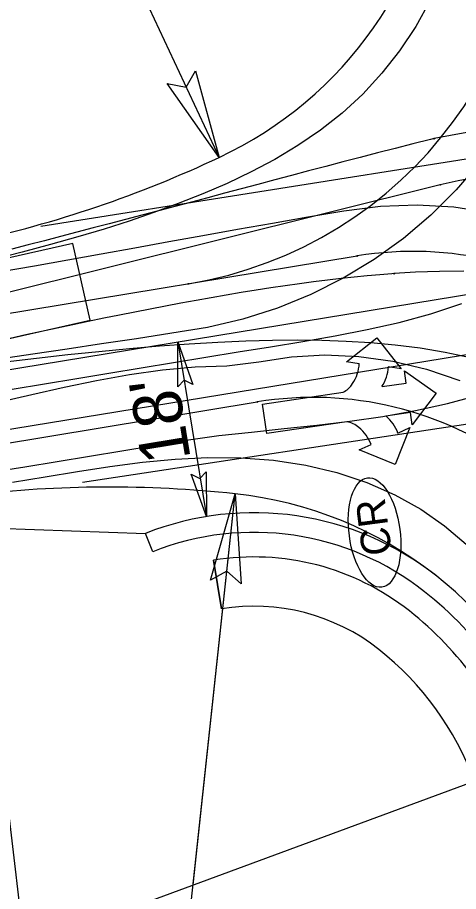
# Model space of a CAD drawing. Extents: x 2367848 to 2369479, y 800728 to 808616.
# Drawn here: x 2368311.6 to 2368356.4, y 807886 to 807974.9 of the extents above; entities that cross this region are included whole.
import ezdxf

# ---------------------------------------------------------------- set-up
doc = ezdxf.new("R2010")
doc.units = 0
for name, color, linetype in [('Default', 7, 'Continuous'), ('Prop AutoTurn Projected Path', 7, 'Continuous'), ('Prop AutoTurn Simulation', 7, 'Continuous'), ('Prop Conc 2ft 6in Curb and Gutter', 7, 'Continuous'), ('Prop Conc 4in Sidewalk', 7, 'Continuous'), ('Prop Dimension', 7, 'Continuous'), ('Prop Dimension Text', 7, 'Continuous'), ('Prop EOT', 7, 'Continuous'), ('Prop Horizontal Alignment', 7, 'Continuous'), ('Prop Lane Arrow CELL', 7, 'Continuous'), ('Prop Paved Shoulder', 7, 'Continuous'), ('Prop Shade Light', 7, 'Continuous'), ('Prop Terminator CELL', 7, 'Continuous'), ('Prop WCC CELL', 7, 'Continuous'), ('Prop WCR CELL', 7, 'Continuous'), ('Scratch_Level_0', 7, 'Continuous'), ('Scratch_Level_1', 7, 'Continuous')]:
    doc.layers.add(name, color=color, linetype=linetype)

# ---------------------------------------------------------------- blocks, each defined once
blk = doc.blocks.new('CR')
at = {"layer": 'Prop WCC CELL'}
blk.add_ellipse((0.022, -0.023), major_axis=(5.607, 0), ratio=0.462467, dxfattribs=at)
blk.add_text('CR', height=3, dxfattribs=at).set_placement((-2.335, -1.5))

msp = doc.modelspace()

# ---------------------------------------------------------------- linework, layer by layer
at = {"layer": 'Default'}
for p, q in [((2368447.259, 807974.784), (2368313.924, 807953.632)), ((2368318.181, 807927.648), (2368451.676, 807947.822))]:
    msp.add_line(p, q, dxfattribs=at)
at = {"layer": 'Prop AutoTurn Projected Path'}
for p, q in [((2368204.585, 807927.346), (2368346.13, 807950.643)), ((2368301.356, 807930.099), (2368335.962, 807935.795))]:
    msp.add_line(p, q, dxfattribs=at)
for centre, radius, start, end in [((2368322.121, 807989.257), 42, 279.34665, 7.41804), ((2368351.814, 807916.108), 35, 7.41804, 99.34665), ((2368341.646, 807901.26), 35, 7.41804, 99.34665)]:
    msp.add_arc(centre, radius, start, end, dxfattribs=at)
at = {"layer": 'Prop AutoTurn Simulation'}
for points in [[(2368353.558, 807976.632), (2368352.084, 807973.994), (2368350.439, 807971.521), (2368348.636, 807969.222), (2368346.685, 807967.102), (2368344.601, 807965.17), (2368342.398, 807963.43), (2368340.099, 807961.871), (2368337.733, 807960.465), (2368335.321, 807959.189), (2368332.876, 807958.024), (2368330.408, 807956.954), (2368327.922, 807955.967), (2368325.423, 807955.049), (2368322.915, 807954.193), (2368320.378, 807953.384), (2368317.71, 807952.585), (2368314.924, 807951.799), (2368312.042, 807951.032), (2368309.084, 807950.286)], [(2368358.574, 807960.118), (2368356.202, 807957.36), (2368353.612, 807954.79), (2368350.82, 807952.426), (2368347.845, 807950.284), (2368344.704, 807948.379), (2368341.417, 807946.725), (2368338.005, 807945.335), (2368334.489, 807944.216), (2368330.892, 807943.378), (2368327.26, 807942.782), (2368323.668, 807942.231), (2368320.117, 807941.697), (2368316.602, 807941.174), (2368313.119, 807940.657), (2368309.664, 807940.143)], [(2368359.637, 807955.047), (2368355.952, 807955.609), (2368352.223, 807955.823), (2368348.483, 807955.684), (2368344.769, 807955.199), (2368341.112, 807954.588), (2368337.507, 807953.962), (2368333.949, 807953.33), (2368330.431, 807952.697), (2368326.948, 807952.067), (2368323.496, 807951.443), (2368320.068, 807950.826), (2368316.662, 807950.216), (2368313.273, 807949.613), (2368309.9, 807949.017)], [(2368357.642, 807940.281), (2368355.074, 807940.837), (2368352.521, 807941.262), (2368349.989, 807941.579), (2368347.48, 807941.806), (2368344.993, 807941.956), (2368342.528, 807942.042), (2368340.081, 807942.072), (2368337.517, 807942.052), (2368334.798, 807941.98), (2368331.957, 807941.857), (2368329.02, 807941.684), (2368326.009, 807941.464), (2368322.939, 807941.203), (2368319.824, 807940.905), (2368316.674, 807940.573), (2368313.496, 807940.212), (2368310.296, 807939.826)], [(2368309.726, 807935.801), (2368313, 807936.559), (2368316.29, 807937.304), (2368319.606, 807937.992), (2368322.947, 807938.586), (2368326.296, 807939.054), (2368329.623, 807939.375), (2368332.865, 807939.463), (2368336.131, 807939.877), (2368339.442, 807940.376), (2368342.835, 807940.577), (2368346.284, 807940.435), (2368349.75, 807939.95), (2368353.193, 807939.127), (2368356.576, 807937.97)], [(2368311.064, 807927.643), (2368314.36, 807928.186), (2368317.656, 807928.726), (2368320.957, 807929.234), (2368324.269, 807929.666), (2368327.594, 807929.981), (2368330.929, 807930.142), (2368334.267, 807930.113), (2368337.595, 807929.862), (2368340.888, 807929.361), (2368344.069, 807928.605), (2368347.097, 807927.598), (2368349.945, 807926.351), (2368352.592, 807924.88), (2368355.021, 807923.205), (2368357.221, 807921.347)]]:
    msp.add_lwpolyline(points, dxfattribs=at)
for centre in [(2368346.13, 807950.643), (2368346.13, 807950.643), (2368328.943, 807947.815), (2368328.943, 807947.815), (2368335.962, 807935.795), (2368335.962, 807935.795)]:
    msp.add_circle(centre, 0.0417, dxfattribs=at)
at = {"layer": 'Prop Conc 2ft 6in Curb and Gutter'}
msp.add_line((2368325.314, 807920.561), (2368324.578, 807922.42), dxfattribs=at)
for centre, radius, start, end in [((2368335.625, 807894.528), 28, 51.68711, 111.60793), ((2368329.426, 807886.682), 38, 20.2566, 51.68711)]:
    msp.add_arc(centre, radius, start, end, dxfattribs=at)
at = {"layer": 'Prop Conc 4in Sidewalk'}
msp.add_line((2368332.311, 807914.759), (2368331.503, 807919.693), dxfattribs=at)
for centre, radius, start, end in [((2368335.625, 807894.528), 25.5, 51.68711, 99.30395), ((2368335.625, 807894.528), 20.5, 51.68711, 99.30395), ((2368329.426, 807886.682), 35.5, 20.2566, 51.68711), ((2368329.426, 807886.682), 30.5, 20.2566, 51.68711)]:
    msp.add_arc(centre, radius, start, end, dxfattribs=at)
at = {"layer": 'Prop Dimension'}
for p, q in [((2368281.057, 808069.281), (2368332.09, 807960.673)), ((2368315.079, 807996.876), (2368332.09, 807960.673)), ((2368327.865, 807941.897), (2368330.775, 807924.134)), ((2368320.889, 807807.139), (2368333.694, 807926.454)), ((2368329.426, 807886.682), (2368333.694, 807926.454))]:
    msp.add_line(p, q, dxfattribs=at)
at = {"layer": 'Prop Dimension Text'}
for p, q in [((2368320.889, 807807.139), (2368306.862, 807926.316)), ((2368254.374, 807858.984), (2368366.952, 807900.531))]:
    msp.add_line(p, q, dxfattribs=at)
at = {"layer": 'Prop EOT'}
for centre, radius, start, end in [((2368315.079, 807996.876), 40, 295.16773, 354.57947), ((2368281.057, 808069.281), 120, 282.32916, 295.16773), ((2368320.889, 807807.139), 120, 83.87456, 96.71313), ((2368329.426, 807886.682), 40, 20.2566, 83.87456)]:
    msp.add_arc(centre, radius, start, end, dxfattribs=at)
at = {"layer": 'Prop Horizontal Alignment'}
msp.add_line((2368281.913, 807934.369), (2368381.597, 807950.7), dxfattribs=at)
at = {"layer": 'Prop Lane Arrow CELL'}
for p, q in [((2368345.03, 807939.882), (2368348.125, 807942.304)), ((2368348.125, 807942.304), (2368350.602, 807939.167)), ((2368346.34, 807939.679), (2368345.03, 807939.882)), ((2368350.602, 807939.167), (2368349.292, 807939.37)), ((2368351.11, 807937.713), (2368350.927, 807938.968)), ((2368350.927, 807938.968), (2368354.167, 807936.681)), ((2368348.649, 807937.355), (2368351.11, 807937.713)), ((2368336.493, 807935.583), (2368344.694, 807936.778)), ((2368354.167, 807936.681), (2368351.728, 807933.468)), ((2368336.929, 807932.592), (2368336.493, 807935.583)), ((2368351.545, 807934.723), (2368349.037, 807934.357)), ((2368351.728, 807933.468), (2368351.545, 807934.723)), ((2368345.081, 807933.781), (2368336.929, 807932.592)), ((2368351.474, 807933.185), (2368350.002, 807929.423)), ((2368350.276, 807932.616), (2368351.474, 807933.185)), ((2368346.337, 807930.909), (2368347.535, 807931.478)), ((2368350.002, 807929.423), (2368346.337, 807930.909))]:
    msp.add_line(p, q, dxfattribs=at)
for centre, radius, start, end in [((2368342.347, 807939.906), 3.996, 325.72802, 356.9407), ((2368345.304, 807939.557), 3.996, 326.53448, 357.31095), ((2368343.694, 807938.821), 2.275, 296.22016, 329.21811), ((2368346.511, 807931.279), 3.996, 19.55515, 50.44484), ((2368344.757, 807931.525), 2.275, 47.3644, 82.13042), ((2368343.776, 807930.1), 3.996, 19.92434, 50.85448)]:
    msp.add_arc(centre, radius, start, end, dxfattribs=at)
at = {"layer": 'Prop Paved Shoulder'}
msp.add_line((2368285.416, 807923.792), (2368324.578, 807922.42), dxfattribs=at)
msp.add_arc((2368335.625, 807894.528), 30, 51.68711, 111.60793, dxfattribs=at)
at = {"layer": 'Prop Shade Light'}
msp.add_line((2368331.503, 807919.693), (2368332.311, 807914.759), dxfattribs=at)
for centre, radius, start, end in [((2368335.625, 807894.528), 25.5, 51.68711, 99.30395), ((2368335.625, 807894.528), 20.5, 51.68711, 99.30395), ((2368329.426, 807886.682), 35.5, 20.2566, 51.68711), ((2368329.426, 807886.682), 30.5, 20.2566, 51.68711)]:
    msp.add_arc(centre, radius, start, end, dxfattribs=at)
at = {"layer": 'Prop Terminator CELL'}
for points in [[(2368329.665, 807969.478), (2368332.09, 807960.673), (2368326.793, 807968.184), (2368328.73, 807967.823)], [(2368327.858, 807937.331), (2368327.865, 807941.897), (2368329.415, 807937.571), (2368328.529, 807938.003)], [(2368330.771, 807928.7), (2368330.775, 807924.134), (2368329.215, 807928.456), (2368330.102, 807928.026)], [(2368331.193, 807917.67), (2368333.694, 807926.454), (2368334.319, 807917.285), (2368332.851, 807918.599)]]:
    msp.add_lwpolyline(points, close=True, dxfattribs=at)
at = {"layer": 'Scratch_Level_0'}
for p, q in [((2368354.563, 807957.874), (2368285.597, 807940.681)), ((2368317.2, 807951.912), (2368282.278, 807944.032)), ((2368318.96, 807944.108), (2368317.2, 807951.912)), ((2368284.038, 807936.229), (2368318.96, 807944.108))]:
    msp.add_line(p, q, dxfattribs=at)
for points in [[(2368357.267, 807963.209), (2368353.96, 807962.578)], [(2368353.96, 807962.578), (2368353.596, 807962.491), (2368351.782, 807962.042), (2368349.983, 807961.589), (2368348.198, 807961.133), (2368346.426, 807960.674), (2368344.666, 807960.215), (2368342.917, 807959.756), (2368341.179, 807959.296), (2368339.45, 807958.838), (2368337.731, 807958.381), (2368336.02, 807957.926), (2368334.317, 807957.473), (2368332.621, 807957.022), (2368330.931, 807956.573), (2368329.247, 807956.126), (2368327.569, 807955.681), (2368325.895, 807955.238), (2368324.226, 807954.798), (2368322.562, 807954.36), (2368320.901, 807953.924), (2368319.243, 807953.49), (2368317.589, 807953.058), (2368315.937, 807952.627), (2368314.288, 807952.198), (2368312.642, 807951.771), (2368310.997, 807951.346)], [(2368349.892, 807948.844), (2368349.651, 807948.827), (2368348.421, 807948.73), (2368347.146, 807948.617), (2368345.831, 807948.488), (2368344.48, 807948.343), (2368343.098, 807948.182), (2368341.688, 807948.006), (2368340.253, 807947.816), (2368338.797, 807947.611), (2368337.322, 807947.393), (2368335.83, 807947.162), (2368334.324, 807946.919), (2368332.805, 807946.665), (2368331.275, 807946.401), (2368329.735, 807946.126), (2368328.186, 807945.842), (2368326.629, 807945.549), (2368325.066, 807945.248), (2368323.497, 807944.94), (2368321.922, 807944.625), (2368320.343, 807944.303), (2368318.759, 807943.975), (2368317.172, 807943.641), (2368315.582, 807943.303), (2368313.989, 807942.959), (2368312.393, 807942.611), (2368310.795, 807942.259)], [(2368356.978, 807949.111), (2368354.512, 807949.077), (2368352.07, 807948.98), (2368349.892, 807948.844)]]:
    msp.add_lwpolyline(points, dxfattribs=at)
for centre in [(2368353.96, 807962.578), (2368353.96, 807962.578), (2368354.563, 807957.874), (2368354.563, 807957.874), (2368349.892, 807948.844), (2368349.892, 807948.844)]:
    msp.add_circle(centre, 0.0417, dxfattribs=at)
msp.add_arc((2368363.029, 807923.914), 35, 7.41804, 103.99856, dxfattribs=at)
at = {"layer": 'Scratch_Level_1'}
msp.add_line((2368282.883, 807928.448), (2368360.8, 807941.212), dxfattribs=at)
for points in [[(2368311.004, 807937.108), (2368314.292, 807937.647), (2368317.58, 807938.185), (2368320.867, 807938.724), (2368324.155, 807939.262), (2368327.443, 807939.801), (2368330.73, 807940.34), (2368334.018, 807940.878), (2368337.306, 807941.417), (2368340.593, 807941.956), (2368343.876, 807942.52), (2368347.147, 807943.151), (2368350.396, 807943.889), (2368353.608, 807944.769), (2368356.766, 807945.824)], [(2368309.01, 807928.675), (2368312.298, 807929.213), (2368315.585, 807929.752), (2368318.873, 807930.29), (2368322.161, 807930.829), (2368325.448, 807931.368), (2368328.736, 807931.906), (2368332.036, 807932.371), (2368335.356, 807932.734), (2368338.684, 807933.094), (2368342.028, 807933.434), (2368345.381, 807933.826), (2368348.73, 807934.309), (2368352.053, 807934.91), (2368355.316, 807935.64), (2368358.477, 807936.497)]]:
    msp.add_lwpolyline(points, dxfattribs=at)

# ---------------------------------------------------------------- block references
at = {"layer": 'Prop WCR CELL', "rotation": 97.54241161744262}
msp.add_blockref('CR', (2368347.875, 807922.492), dxfattribs=at)

# ---------------------------------------------------------------- texts
at = {"layer": 'Prop Dimension'}
msp.add_text("18'", height=5, rotation=99.30395, dxfattribs=at).set_placement((2368329.194, 807930.004))

doc.saveas('drawing.dxf')
